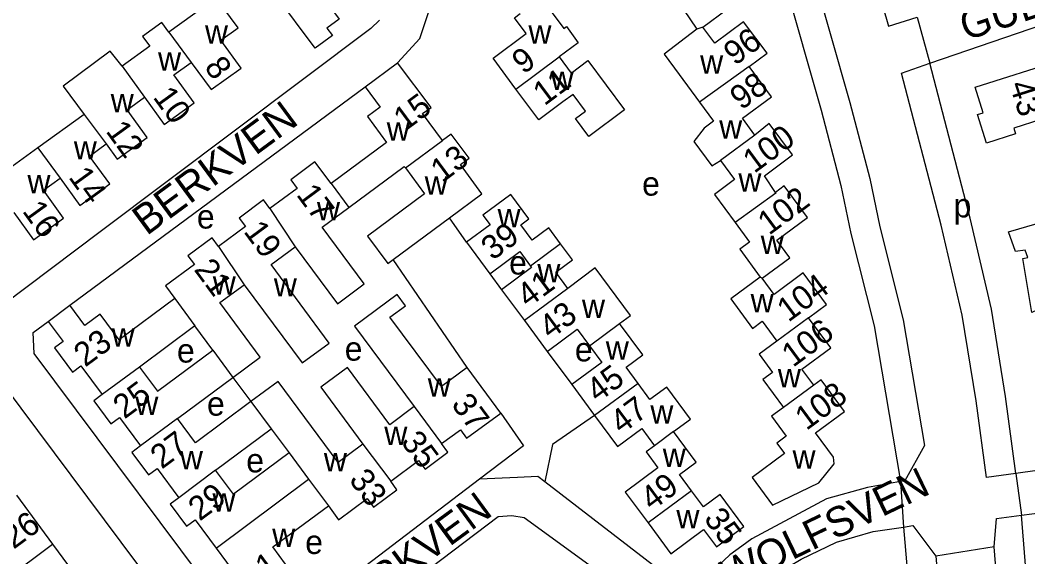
# Model space of a CAD drawing. Extents: x 162667 to 164645, y 379003 to 382150.
# Drawn here: x 163796.8 to 163965.8, y 381199.7 to 381289.7 of the extents above; entities that cross this region are included whole.
import ezdxf

# ---------------------------------------------------------------- set-up
doc = ezdxf.new("R2010")
doc.units = 0
for name, color, linetype in [('BLT_Basislijn', 7, 'Continuous'), ('BLT_Bebouwing', 7, 'Continuous'), ('BLT_Centroide', 7, 'Continuous'), ('BLT_Huisnummer', 7, 'Continuous'), ('BLT_Huisnummer_ tussenligend', 7, 'Continuous'), ('BLT_Onderverdeling_panden', 7, 'Continuous'), ('BLT_Straatnaam', 7, 'Continuous'), ('BLT_Vlakafsluiter', 7, 'Continuous')]:
    doc.layers.add(name, color=color, linetype=linetype)

msp = doc.modelspace()

# ---------------------------------------------------------------- linework, layer by layer
at = {"layer": 'BLT_Basislijn'}
for p, q in [((163857.06, 381289.7), (163855.61, 381288.32)), ((163855.61, 381288.32), (163810.21, 381254.21)), ((163871.62, 381252.46), (163868.77, 381256.56)), ((163810.21, 381254.21), (163793.87, 381241.9)), ((163871.74, 381231.45), (163859.32, 381249.56)), ((163875.56, 381247.15), (163877.52, 381244.5)), ((163885.19, 381234.14), (163889.31, 381228.58))]:
    msp.add_line(p, q, dxfattribs=at)
for points in [[(163855.13, 381422.97), (163864.61, 381416.46), (163891.03, 381396.1), (163907.85, 381381.79), (163912.89, 381376.55), (163919.26, 381366.91), (163923.4, 381355.76), (163926.9, 381342.69), (163942.45, 381288.67), (163947.21, 381290.21)], [(163949.34, 381282.46), (163999.85, 381299.78), (164007.17, 381302.53), (164016.31, 381307.11), (164020.89, 381310.16), (164024.54, 381313.82), (164065.11, 381360.24), (164089.95, 381379.6)], [(163906.55, 381360.85), (163908.58, 381360.85), (163910.72, 381359.8), (163912.63, 381357.25), (163913.2, 381355.76), (163935.93, 381275.91), (163939.29, 381263.14), (163940.99, 381255.05), (163944.91, 381239.45), (163948.48, 381218.36), (163945.14, 381212.48), (163944.42, 381212.35)], [(163906.55, 381360.85), (163931.11, 381274.59), (163934.43, 381261.99), (163936.12, 381253.93), (163940.01, 381238.43), (163944.42, 381212.35)], [(163860.07, 381282.54), (163863.82, 381286.61), (163866.73, 381295.31), (163856.66, 381320.67), (163856.65, 381321.6), (163857.83, 381324.94), (163861.07, 381328.11)], [(163963.79, 381213.71), (163958.84, 381213.02), (163957.12, 381225.86), (163954.79, 381240.25), (163951.24, 381255.31), (163944.6, 381280.83), (163949.34, 381282.46)], [(163963.79, 381213.71), (163962.07, 381226.59), (163959.69, 381241.23), (163956.1, 381256.51), (163949.34, 381282.46)], [(163805.13, 381241.89), (163854.63, 381278.51)], [(163822.31, 381130.67), (163818.31, 381128.09), (163813.89, 381126.98), (163812.29, 381126.9), (163806.46, 381127.93), (163791.01, 381137.26), (163784.57, 381142.27), (163774.34, 381150.78), (163761.37, 381164.77), (163759.3, 381167.59), (163747.46, 381186.8), (163743.42, 381196.09), (163738.32, 381209.11), (163734.13, 381224.16), (163734.29, 381230.05), (163735.56, 381233.49), (163739.65, 381238.21), (163767.49, 381258.57), (163771.7, 381258.34), (163830.43, 381179.71)], [(163873.85, 381212.75), (163838.97, 381186.21), (163834.92, 381186.36), (163834.32, 381186.73), (163799.13, 381233.78), (163798.96, 381237.33), (163801.48, 381239.19)], [(164044.41, 381235.94), (163985.37, 381217.27), (163977.29, 381215.59), (163963.79, 381213.71)], [(163964.75, 381206.69), (163976.84, 381208.27), (163993.91, 381211.78), (164048.49, 381228.82)], [(163877.4, 381223.82), (163881.2, 381218.34), (163873.85, 381212.75)], [(163893.14, 381223.4), (163886.07, 381218.55), (163884.76, 381212.29)], [(163884.76, 381212.29), (163883.63, 381213.17), (163880.22, 381213.02), (163873.85, 381212.75)], [(163944.42, 381212.35), (163938.89, 381211.34), (163932, 381209.44), (163919.48, 381202.75), (163917.8, 381201.5), (163915.81, 381200.05), (163911.97, 381196.39), (163906.91, 381195.58), (163904.28, 381197.24), (163884.76, 381212.29)], [(163841.42, 381179.33), (163842.85, 381180.63), (163876.98, 381206.48), (163879.27, 381206.63), (163881.34, 381206.32), (163898.32, 381193.98), (163900.46, 381192.06), (163906.61, 381184.27), (163916.2, 381158.97), (163915.43, 381155.88), (163914.96, 381155.27), (163891.88, 381138.2)], [(163960.16, 381201.36), (163960.53, 381206.14), (163964.75, 381206.69)], [(163975.42, 381073.66), (163964.75, 381206.69)], [(163884.58, 381124.62), (163921.36, 381151.86), (163923.08, 381158.78), (163923.24, 381160.59), (163914.43, 381183.95), (163916.39, 381191.02), (163923.62, 381196.85), (163927.79, 381199.34), (163933.69, 381202.17), (163939.83, 381203.95), (163944.95, 381204.71)], [(163944.95, 381204.71), (163946.5, 381204.95), (163950.39, 381199.85)], [(163944.95, 381204.71), (163956.39, 381072.34)], [(163975.42, 381073.66), (163970.48, 381072.75), (163960.16, 381201.36)], [(163950.39, 381199.85), (163961.1, 381075.93), (163959.26, 381072.84), (163956.39, 381072.34)]]:
    msp.add_lwpolyline(points, dxfattribs=at)
at = {"layer": 'BLT_Bebouwing'}
for p, q in [((163854.63, 381278.51), (163860.07, 381282.54)), ((163807.49, 381273.9), (163799.76, 381268.31)), ((163799.76, 381268.31), (163791.94, 381262.64)), ((163859.32, 381249.56), (163868.77, 381256.56)), ((163871.62, 381252.46), (163875.56, 381247.15)), ((163877.52, 381244.5), (163881.35, 381239.32)), ((163801.48, 381239.19), (163805.13, 381241.89)), ((163826.08, 381238.42), (163816.78, 381231.53)), ((163829.08, 381234.36), (163826.08, 381238.42)), ((163881.35, 381239.32), (163885.19, 381234.14)), ((163877.4, 381223.82), (163871.74, 381231.45)), ((163823.17, 381222.91), (163832.47, 381229.8)), ((163832.47, 381229.8), (163835.49, 381225.74)), ((163889.31, 381228.58), (163893.14, 381223.4)), ((163829.57, 381214.24), (163838.87, 381221.18)), ((163838.87, 381221.18), (163841.88, 381217.14)), ((163796.17, 381210.03), (163802.23, 381201.84)), ((163802.23, 381201.84), (163808.31, 381193.64))]:
    msp.add_line(p, q, dxfattribs=at)
for points in [[(163911.3, 381288.52), (163915.39, 381291.52), (163913.09, 381294.41), (163918.17, 381298.18), (163914.24, 381303.47), (163912.43, 381302.14)], [(163846.67, 381299.42), (163849.06, 381301.18), (163852.71, 381296.22), (163848.12, 381292.84), (163850.29, 381289.88), (163848.24, 381288.37), (163849.15, 381287.12), (163846.24, 381284.98), (163839.51, 381294.13), (163841.7, 381295.76)], [(163907.43, 381298.46), (163906.06, 381297.25), (163908.25, 381293.95), (163906.99, 381293.1), (163910.27, 381288.18)], [(163825.49, 381282.61), (163828.8, 381278.04), (163833.83, 381281.67), (163830.45, 381286.34), (163833.32, 381288.41), (163829.67, 381293.45), (163821.72, 381287.69)], [(163884.17, 381293.42), (163887.97, 381288.31), (163888.4, 381288.62), (163890.38, 381285.88), (163887.18, 381283.54)], [(163879.94, 381278.14), (163876.09, 381283.31), (163881.67, 381287.47), (163879.72, 381290.1), (163880.65, 381290.8)], [(163821.72, 381287.69), (163820.55, 381289.31), (163817.31, 381286.97), (163818.51, 381285.31), (163813.87, 381281.95)], [(163919.08, 381281.91), (163922.06, 381284.13), (163918.13, 381289.42), (163913.28, 381285.84), (163911.3, 381288.52)], [(163910.27, 381288.18), (163904.77, 381283.99), (163907.31, 381280.56), (163910.72, 381275.95)], [(163813.87, 381281.95), (163811.87, 381284.5), (163804, 381278.65), (163807.49, 381273.9)], [(163887.18, 381283.54), (163889.2, 381280.83), (163892, 381282.91), (163898.15, 381274.65), (163892.14, 381270.18), (163889.91, 381273.21), (163891.6, 381274.46), (163889.51, 381277.24), (163887.82, 381275.98), (163883.79, 381272.97), (163879.94, 381278.14)], [(163817.61, 381276.77), (163820.92, 381272.2), (163825.95, 381275.84), (163822.57, 381280.5), (163825.49, 381282.61)], [(163867.63, 381269.52), (163864.29, 381274.02), (163865.71, 381275.07), (163860.07, 381282.54)], [(163920.02, 381270.43), (163917.94, 381273.26), (163922.82, 381276.86), (163919.08, 381281.91)], [(163971.45, 381283.04), (163972.81, 381278.75), (163977.57, 381280.27), (163979.78, 381273.31), (163973.52, 381271.33), (163972.52, 381274.47), (163963.44, 381271.59), (163963.74, 381270.63), (163958.87, 381269.09), (163957.36, 381273.88), (163958.32, 381274.18), (163956.96, 381278.45), (163971.45, 381283.04)], [(163854.63, 381278.51), (163857.15, 381275.11), (163855.02, 381273.54), (163858.24, 381269.19), (163848.92, 381262.29)], [(163811.22, 381268.93), (163813.07, 381266.38), (163818.07, 381270), (163814.7, 381274.66), (163817.61, 381276.77)], [(163910.72, 381275.95), (163913.08, 381272.76), (163911.48, 381271.57), (163909.76, 381269.35), (163912.77, 381265.28), (163914.23, 381266.17)], [(163923.46, 381260.82), (163921.62, 381263.6), (163926.33, 381267.09), (163922.41, 381272.39), (163920.02, 381270.43)], [(163868.77, 381256.56), (163874.23, 381260.6), (163870.62, 381265.47), (163872.07, 381266.54), (163869.07, 381270.59), (163867.63, 381269.52)], [(163803.47, 381263.18), (163806.78, 381258.61), (163811.81, 381262.24), (163808.43, 381266.91), (163811.22, 381268.93)], [(163848.92, 381262.29), (163846.22, 381265.93), (163842.16, 381262.92), (163843.25, 381261.45), (163838.66, 381258.1)], [(163851.89, 381258.27), (163861.21, 381265.18), (163861.4, 381264.91)], [(163861.4, 381264.91), (163864.61, 381260.58), (163855.05, 381253.5), (163858.45, 381248.91), (163859.32, 381249.56)], [(163914.23, 381266.17), (163916.6, 381262.99), (163913.22, 381260.48), (163916.69, 381255.74)], [(163795.72, 381257.43), (163799.03, 381252.85), (163804.06, 381256.49), (163800.68, 381261.16), (163803.47, 381263.18)], [(163921.26, 381246.41), (163925.9, 381249.85), (163923.67, 381252.81), (163928.86, 381256.59), (163924.95, 381261.92), (163923.46, 381260.82)], [(163887.43, 381252.2), (163885.44, 381254.89), (163882.63, 381252.8), (163880.73, 381255.37), (163882.11, 381256.4), (163879.09, 381260.47), (163874.4, 381257), (163875.59, 381255.39), (163871.62, 381252.46)], [(163838.66, 381258.1), (163837.58, 381259.55), (163833.49, 381256.52), (163834.56, 381255.08), (163830.05, 381251.73)], [(163842.91, 381251.7), (163849.98, 381242.15), (163854.46, 381245.48), (163847.43, 381254.97), (163851.89, 381258.27)], [(163984.91, 381254.34), (163986.38, 381245.26), (163982.04, 381244.55), (163981.51, 381247.78), (163978.27, 381246.24), (163978.91, 381242.27), (163971.74, 381243.16), (163966.45, 381240.68), (163964.98, 381249.75), (163965.8, 381249.88), (163965.32, 381251.13), (163963.73, 381250.92), (163962.57, 381254.19), (163970.45, 381256.49), (163971.5, 381253.34), (163976.98, 381254.23), (163977.38, 381251.76), (163980.77, 381252.3), (163980.56, 381253.64), (163984.91, 381254.34)], [(163916.69, 381255.74), (163919.09, 381252.48), (163917.48, 381251.3), (163920.92, 381246.6)], [(163830.05, 381251.73), (163828.98, 381253.18), (163824.93, 381250.18), (163826, 381248.73), (163821.14, 381245.13), (163822.7, 381243.02)], [(163834.36, 381245.34), (163844.09, 381232.21), (163848.61, 381235.56), (163838.87, 381248.71), (163842.91, 381251.7)], [(163888.62, 381244.71), (163886.61, 381247.43), (163889.42, 381249.51), (163887.43, 381252.2)], [(163875.56, 381247.15), (163880.58, 381250.88), (163882.38, 381248.45)], [(163882.38, 381248.45), (163882.55, 381248.22), (163877.52, 381244.5)], [(163897.33, 381238.83), (163899.16, 381240.2), (163893.25, 381248.15), (163888.62, 381244.71)], [(163920.92, 381246.6), (163915.97, 381242.97), (163919.62, 381238.02), (163921.23, 381239.21), (163923.69, 381235.88)], [(163929.03, 381239.81), (163932, 381242), (163928.09, 381247.31), (163923.24, 381243.72), (163921.26, 381246.41)], [(163832.47, 381229.8), (163837.06, 381233.19), (163830.29, 381242.33), (163834.36, 381245.34)], [(163822.7, 381243.02), (163813.39, 381236.11), (163810.19, 381240.42), (163807.62, 381238.52), (163805.13, 381241.89)], [(163871.74, 381231.45), (163867.43, 381228.26), (163858.8, 381239.9), (163861.39, 381241.82), (163860.01, 381243.68), (163852.88, 381238.39), (163862.88, 381224.9)], [(163929.88, 381228.47), (163927.89, 381231.17), (163932.76, 381234.75), (163929.03, 381239.81)], [(163801.48, 381239.19), (163803.98, 381235.82), (163802.53, 381234.75), (163805.54, 381230.68), (163806.98, 381231.76), (163810.56, 381226.93)], [(163885.19, 381234.14), (163890.21, 381237.86), (163892.27, 381235.08)], [(163900.41, 381228.8), (163898.4, 381231.51), (163901.22, 381233.59), (163897.33, 381238.83)], [(163892.27, 381235.08), (163894.33, 381232.3), (163889.31, 381228.58)], [(163923.69, 381235.88), (163920.72, 381233.69), (163922.96, 381230.64), (163921.36, 381229.46), (163924.82, 381224.77)], [(163816.78, 381231.53), (163819.79, 381227.47), (163829.08, 381234.36)], [(163862.88, 381224.9), (163858.79, 381221.86), (163851.68, 381231.46), (163847.2, 381228.14), (163854.26, 381218.6)], [(163924.82, 381224.77), (163922.82, 381223.29), (163925.27, 381219.96), (163923.67, 381218.78), (163924.96, 381217.03), (163919.55, 381213.04), (163922.99, 381208.37), (163930.72, 381212.1), (163933.33, 381215.33), (163933.19, 381216.43), (163930.2, 381220.5), (163935.06, 381224.08), (163931.14, 381229.4), (163929.88, 381228.47)], [(163854.26, 381218.6), (163850.13, 381215.54), (163840.06, 381229.13), (163835.49, 381225.74)], [(163906.39, 381220.71), (163909.21, 381222.8), (163905.23, 381228.18), (163902.42, 381226.09), (163900.41, 381228.8)], [(163810.56, 381226.93), (163809.12, 381225.86), (163811.98, 381222), (163813.42, 381223.06), (163816.95, 381218.3)], [(163835.49, 381225.74), (163826.18, 381218.84), (163823.17, 381222.91)], [(163867.47, 381218.7), (163870.61, 381221.02), (163871.67, 381219.58), (163877.4, 381223.82)], [(163893.14, 381223.4), (163896.98, 381218.22), (163901.04, 381221.22), (163903.18, 381218.33)], [(163909.37, 381210.8), (163907.37, 381213.51), (163910.18, 381215.6), (163906.39, 381220.71)], [(163816.95, 381218.3), (163815.51, 381217.23), (163818.31, 381213.44), (163819.75, 381214.51), (163823.37, 381209.62)], [(163858.94, 381212.42), (163863.61, 381215.86), (163864.69, 381214.41), (163868.53, 381217.27), (163867.47, 381218.7)], [(163903.18, 381218.33), (163901.79, 381217.3), (163903.76, 381214.64), (163898.27, 381210.57), (163902.1, 381205.41)], [(163841.88, 381217.14), (163832.58, 381210.21), (163829.57, 381214.24)], [(163848.47, 381208.25), (163850.2, 381205.92), (163855, 381209.47), (163856.06, 381208.03), (163859.96, 381210.92), (163858.94, 381212.42)], [(163902.1, 381205.41), (163905.93, 381200.23), (163911.39, 381204.28), (163913.56, 381201.36), (163918.18, 381204.79), (163914.19, 381210.18), (163911.38, 381208.09), (163909.37, 381210.8)], [(163823.37, 381209.62), (163821.93, 381208.54), (163824.68, 381204.83), (163826.13, 381205.9), (163829.64, 381201.19)], [(163829.64, 381201.19), (163833.14, 381196.49), (163831.69, 381195.42), (163834.69, 381191.36), (163842.37, 381197.05), (163839.17, 381201.36), (163848.47, 381208.25)]]:
    msp.add_lwpolyline(points, dxfattribs=at)
at = {"layer": 'BLT_Onderverdeling_panden'}
for p, q in [((163911.3, 381288.52), (163910.27, 381288.18)), ((163821.72, 381287.69), (163825.49, 381282.61)), ((163879.94, 381278.14), (163887.18, 381283.54)), ((163813.87, 381281.95), (163817.61, 381276.77)), ((163919.08, 381281.91), (163910.72, 381275.95)), ((163807.49, 381273.9), (163811.22, 381268.93)), ((163920.02, 381270.43), (163914.23, 381266.17)), ((163799.76, 381268.31), (163803.47, 381263.18)), ((163861.4, 381264.91), (163867.63, 381269.52)), ((163848.92, 381262.29), (163851.89, 381258.27)), ((163838.66, 381258.1), (163842.91, 381251.7)), ((163830.05, 381251.73), (163834.36, 381245.34)), ((163887.43, 381252.2), (163882.38, 381248.45)), ((163921.26, 381246.41), (163920.92, 381246.6)), ((163888.62, 381244.71), (163881.35, 381239.32)), ((163822.7, 381243.02), (163826.08, 381238.42)), ((163929.03, 381239.81), (163923.69, 381235.88)), ((163892.27, 381235.08), (163897.33, 381238.83)), ((163829.08, 381234.36), (163832.47, 381229.8)), ((163816.78, 381231.53), (163810.56, 381226.93)), ((163900.41, 381228.8), (163893.14, 381223.4)), ((163929.88, 381228.47), (163924.82, 381224.77)), ((163835.49, 381225.74), (163838.87, 381221.18)), ((163862.88, 381224.9), (163867.47, 381218.7)), ((163823.17, 381222.91), (163816.95, 381218.3)), ((163906.39, 381220.71), (163903.18, 381218.33)), ((163854.26, 381218.6), (163858.94, 381212.42)), ((163841.88, 381217.14), (163845.17, 381212.71)), ((163829.57, 381214.24), (163823.37, 381209.62)), ((163829.64, 381201.19), (163845.17, 381212.71)), ((163845.17, 381212.71), (163848.47, 381208.25)), ((163909.37, 381210.8), (163902.1, 381205.41)), ((163785.66, 381189.56), (163802.23, 381201.84))]:
    msp.add_line(p, q, dxfattribs=at)
msp.add_lwpolyline([(163923.46, 381260.82), (163923.54, 381260.7), (163916.69, 381255.74)], dxfattribs=at)
at = {"layer": 'BLT_Vlakafsluiter'}
for p, q in [((163947.21, 381290.21), (163949.34, 381282.46)), ((163963.79, 381213.71), (163964.75, 381206.69)), ((163944.42, 381212.35), (163944.95, 381204.71)), ((163960.16, 381201.36), (163950.39, 381199.85))]:
    msp.add_line(p, q, dxfattribs=at)

# ---------------------------------------------------------------- texts
at = {"layer": 'BLT_Centroide'}
for s, p in [('w', (163827.78, 381285.77)), ('w', (163882.03, 381285.75)), ('w', (163819.91, 381281.22)), ('w', (163910.83, 381280.7)), ('w', (163885.76, 381278)), ('w', (163811.97, 381274.23)), ('w', (163858.27, 381269.47)), ('w', (163914.03, 381269.84)), ('w', (163805.78, 381266.33)), ('w', (163798, 381260.66)), ('w', (163864.64, 381260.41)), ('e', (163901.1, 381260.27)), ('w', (163917.25, 381260.94)), ('p', (163953.34, 381256.62)), ('w', (163846.56, 381256.11)), ('w', (163876.85, 381254.98)), ('e', (163826.42, 381254.75)), ('w', (163921, 381250.47)), ('e', (163878.79, 381247.04)), ('w', (163883.53, 381245.75)), ('w', (163829.09, 381243.69)), ('w', (163839.33, 381243.36)), ('w', (163919.3, 381240.7)), ('w', (163891.01, 381239.74)), ('w', (163812.13, 381234.97)), ('e', (163823.08, 381232.28)), ('e', (163851.22, 381232.6)), ('e', (163889.82, 381232.48)), ('w', (163895.01, 381232.75)), ('w', (163923.87, 381228.12)), ('w', (163865.14, 381226.59)), ('w', (163816.09, 381223.48)), ('e', (163828.12, 381223.38)), ('w', (163902.48, 381222.06)), ('w', (163857.86, 381218.44)), ('w', (163904.56, 381214.8)), ('w', (163926.33, 381214.51)), ('w', (163823.57, 381214.38)), ('e', (163834.7, 381213.87)), ('w', (163847.72, 381214.03)), ('w', (163829.03, 381207.3)), ('w', (163906.85, 381204.47)), ('w', (163839.05, 381201.38)), ('e', (163844.59, 381200.19))]:
    msp.add_text(s, height=4, dxfattribs=at).set_placement(p)
at = {"layer": 'BLT_Huisnummer'}
for s, rotation, p in [('96', 36.4468, (163916.67, 381281.95)), ('8', 305.8865, (163827.55, 381281.8)), ('11', 36.7093, (163884.71, 381275.23)), ('43', 287.593, (163962.67, 381278.9)), ('15', 36.5097, (163861.31, 381270.96)), ('100', 36.4468, (163919.9, 381263.9)), ('13', 36.5249, (163867.54, 381262.31)), ('14', 305.8848, (163804.79, 381263.36)), ('17', 306.5059, (163842.99, 381260.42)), ('39', 36.54, (163876.01, 381249.29)), ('21', 306.5059, (163825.82, 381247.86)), ('104', 36.4468, (163925.62, 381238.95)), ('23', 36.5477, (163807.68, 381231.42)), ('45', 36.5343, (163893.65, 381225.45)), ('108', 36.4468, (163928.65, 381220.79)), ('37', 306.5401, (163868.97, 381225.26)), ('27', 36.5477, (163820.53, 381214.31)), ('33', 306.5401, (163851.81, 381212.61)), ('49', 36.5425, (163902.73, 381207.31)), ('35', 306.5468, (163911.33, 381206.09)), ('31', 36.5477, (163835.72, 381194.1))]:
    msp.add_text(s, height=4, rotation=rotation, dxfattribs=at).set_placement(p)
at = {"layer": 'BLT_Huisnummer_ tussenligend'}
for s, rotation, p in [('9', 36.7093, (163881.19, 381280.51)), ('98', 36.4468, (163917.74, 381274.5)), ('10', 305.8848, (163818.94, 381276.77)), ('12', 305.8848, (163811.03, 381271.07)), ('102', 36.4468, (163922.38, 381253.52)), ('16', 305.8848, (163797.03, 381257.67)), ('19', 306.5059, (163834.14, 381254.24)), ('41', 36.5518, (163881.98, 381241.36)), ('43', 36.5321, (163885.71, 381236.06)), ('106', 36.4468, (163926.41, 381231.38)), ('25', 36.5477, (163814.27, 381222.71)), ('47', 36.5363, (163897.63, 381220.15)), ('35', 306.5401, (163860.51, 381218.97)), ('29', 36.5477, (163826.89, 381205.6)), ('26', 36.5047, (163795.68, 381200.88))]:
    msp.add_text(s, height=4, rotation=rotation, dxfattribs=at).set_placement(p)
at = {"layer": 'BLT_Straatnaam'}
for s, rotation, p in [('GULBERGSVEN', 18.1205, (163955.38, 381286.22)), ('BERKVEN', 36.3773, (163818, 381253.46)), ('WOLFSVEN', 25.6382, (163915.88, 381194.14)), ('BERKVEN', 36.2811, (163850.52, 381187.94))]:
    msp.add_text(s, height=5, rotation=rotation, dxfattribs=at).set_placement(p)

doc.saveas('drawing.dxf')
